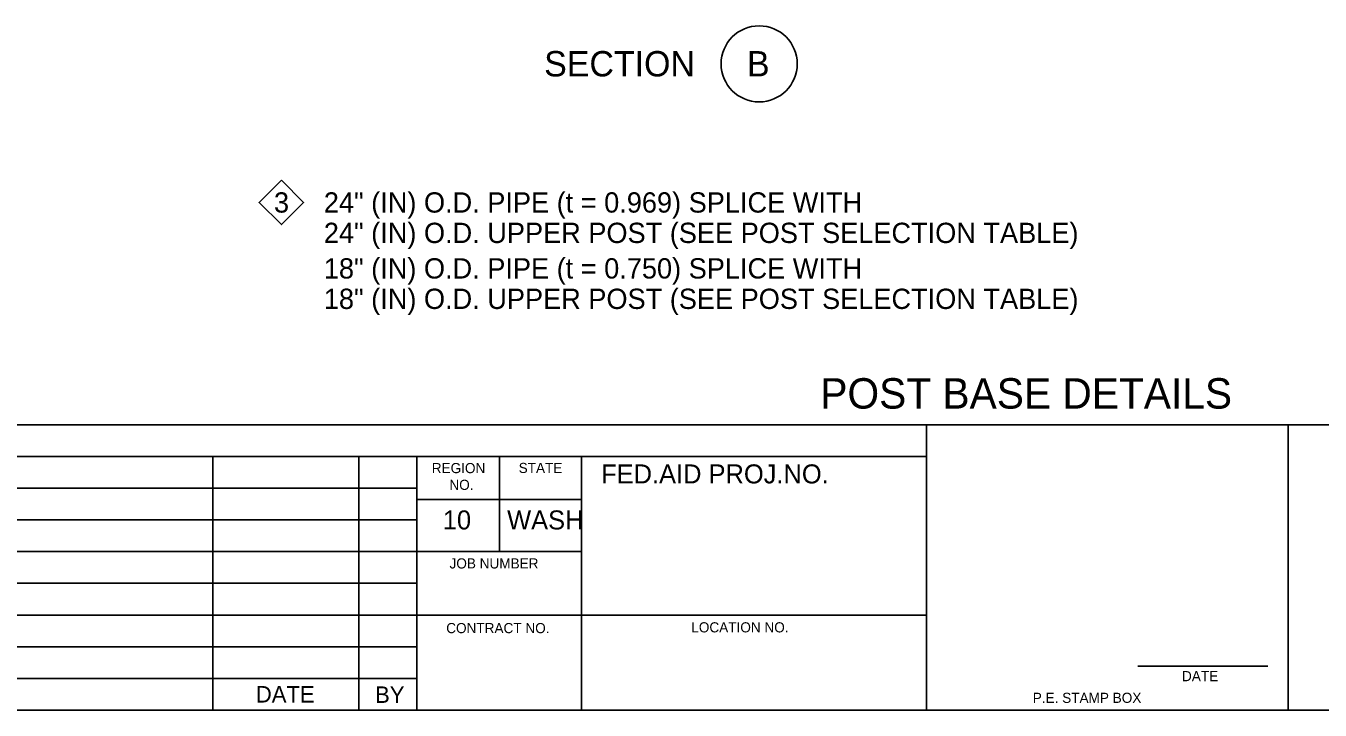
# Model space of a CAD drawing. Extents: x 99862 to 104211, y 98939 to 111076.
# Drawn here: x 100780 to 101800, y 109000 to 109540 of the extents above; entities that cross this region are included whole.
import ezdxf

# ---------------------------------------------------------------- set-up
doc = ezdxf.new("R2010")
doc.units = 0
for name, color, linetype in [('Level 20', 7, 'Continuous'), ('Level 60', 7, 'Continuous'), ('Level 9', 7, 'Continuous')]:
    doc.layers.add(name, color=color, linetype=linetype)

msp = doc.modelspace()

# ---------------------------------------------------------------- linework, layer by layer
at = {"layer": 'Level 20'}
msp.add_lwpolyline([(100981.4, 109418), (100998.9, 109400.4), (100981.4, 109382.9), (100963.8, 109400.4)], close=True, dxfattribs=at)
at = {"layer": 'Level 60'}
for p, q in [((100000, 109225), (103150, 109225)), ((101490.1, 109000), (101490.1, 109225)), ((101775.1, 109000), (101775.1, 109225)), ((100000, 109200), (101490.1, 109200)), ((100927.5, 109200), (100927.5, 109000)), ((101042.5, 109200), (101042.5, 109000)), ((101088.1, 109200), (101088.1, 109000)), ((101153.5, 109125), (101153.5, 109200)), ((101218.1, 109000), (101218.1, 109200)), ((100436.1, 109175), (101088.5, 109175)), ((101218.2, 109166.1), (101088.5, 109166.1)), ((100436.1, 109150), (101088.5, 109150)), ((100000, 109125), (101088.5, 109125)), ((101218.2, 109125), (101088.5, 109125)), ((100000, 109100), (101088.5, 109100)), ((100000, 109075), (101088.5, 109075)), ((101490.1, 109075), (101088.5, 109075)), ((100000, 109050), (101088.5, 109050)), ((101656.7, 109034.6), (101759, 109034.6)), ((100000, 109025), (101088.5, 109025)), ((100000, 109000), (103150, 109000))]:
    msp.add_line(p, q, dxfattribs=at)
at = {"layer": 'Level 9'}
msp.add_circle((101358.1, 109509.7), 30, dxfattribs=at)

# ---------------------------------------------------------------- texts
at = {"layer": 'Level 20'}
for s, height, p in [('SECTION', 20, (101188.6, 109499.8)), ('B', 20, (101348.5, 109499.8)), ('3', 16, (100975.6, 109392.4)), ('24" (IN) O.D. PIPE (t = 0.969) SPLICE WITH', 16, (101014.9, 109392.4)), ('24" (IN) O.D. UPPER POST (SEE POST SELECTION TABLE)', 16, (101014.9, 109368.4)), ('18" (IN) O.D. PIPE (t = 0.750) SPLICE WITH', 16, (101014.9, 109340.4)), ('18" (IN) O.D. UPPER POST (SEE POST SELECTION TABLE)', 16, (101014.9, 109316.4)), ('POST BASE DETAILS', 24, (101406.3, 109237.8))]:
    msp.add_text(s, height=height, dxfattribs=at).set_placement(p)
at = {"layer": 'Level 60'}
for s, height, p in [('REGION', 8, (101100, 109186.9)), ('STATE', 8, (101168.5, 109187)), ('FED.AID PROJ.NO.', 15, (101233.5, 109178.8)), ('NO.', 8, (101113.9, 109173.7)), ('10', 15, (101108.7, 109142.5)), ('WASH', 15, (101159.4, 109142.5)), ('JOB NUMBER', 8, (101114, 109111.7)), ('CONTRACT NO.', 8, (101111.4, 109060.7)), ('LOCATION NO.', 8, (101304.6, 109061.3)), ('DATE', 8.03, (101691.4, 109022.8)), ('DATE', 13, (100961.3, 109006)), ('BY', 13, (101055.3, 109005.7)), ('P.E. STAMP BOX', 8, (101573.8, 109005.7))]:
    msp.add_text(s, height=height, dxfattribs=at).set_placement(p)

doc.saveas('drawing.dxf')
